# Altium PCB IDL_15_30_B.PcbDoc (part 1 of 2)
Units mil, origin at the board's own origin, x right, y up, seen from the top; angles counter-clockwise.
Board outline 4133.86 x 2440.94 mil, 4 copper layers (Top Layer - SIG1, Layer 2 - GND1, Layer 3 - SIG2, Bottom Layer - SIG4), stack 63.086 mil thick; 140 components, 50 nets, 376 pads, 452 vias.
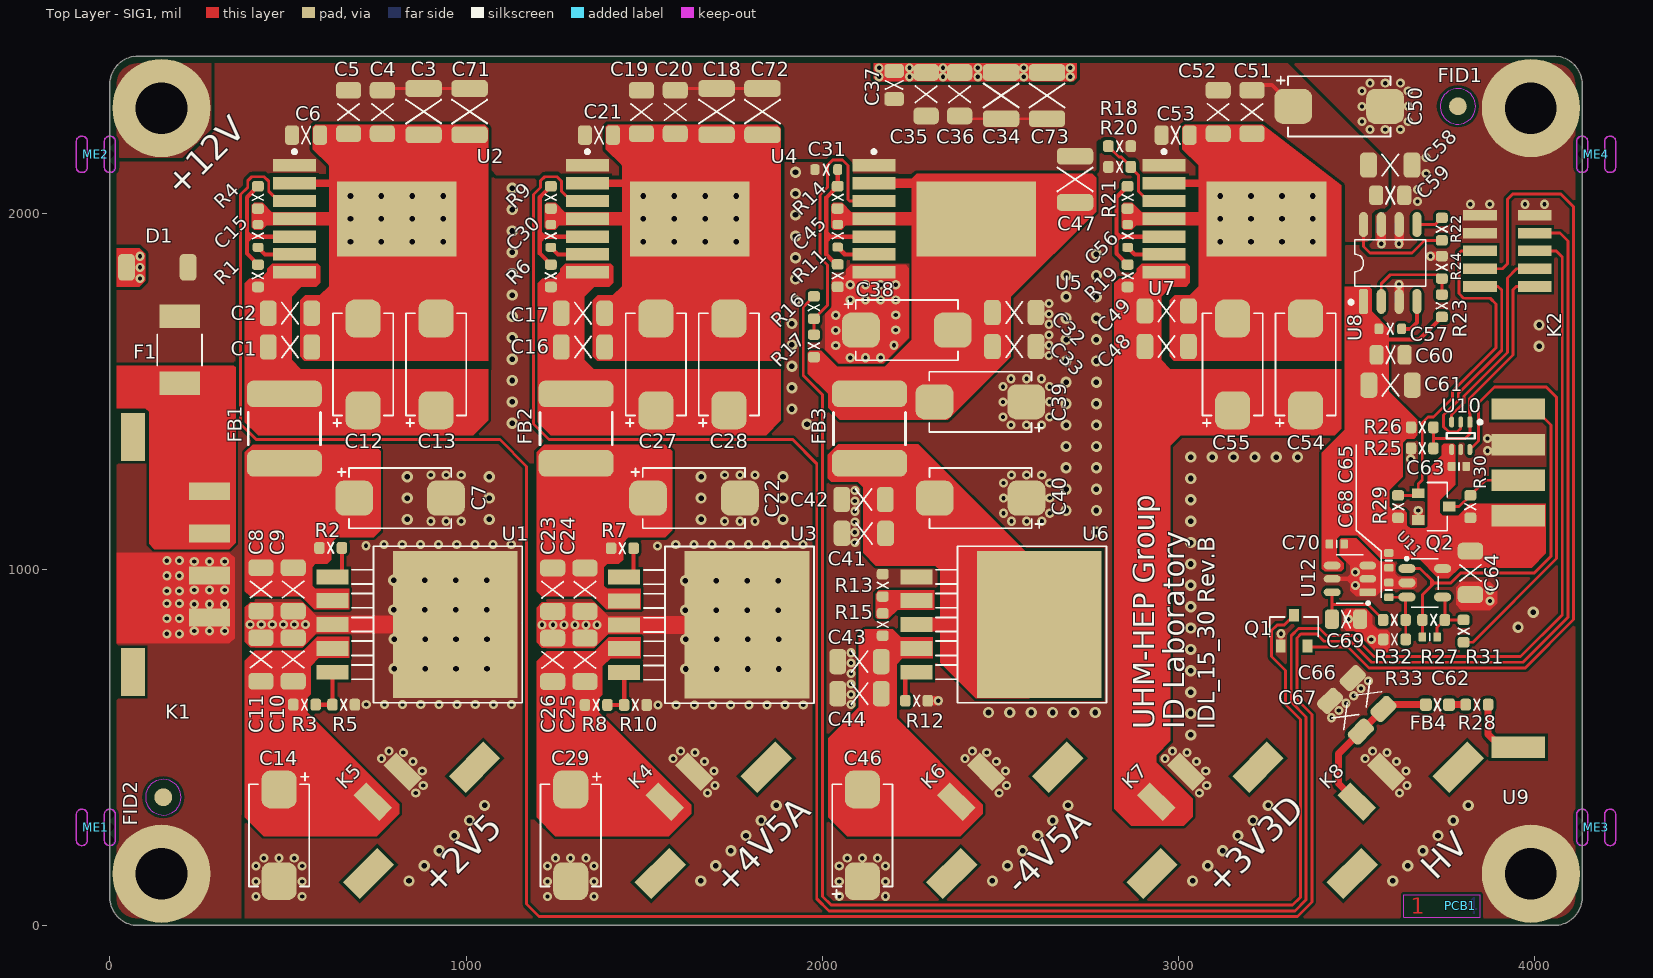
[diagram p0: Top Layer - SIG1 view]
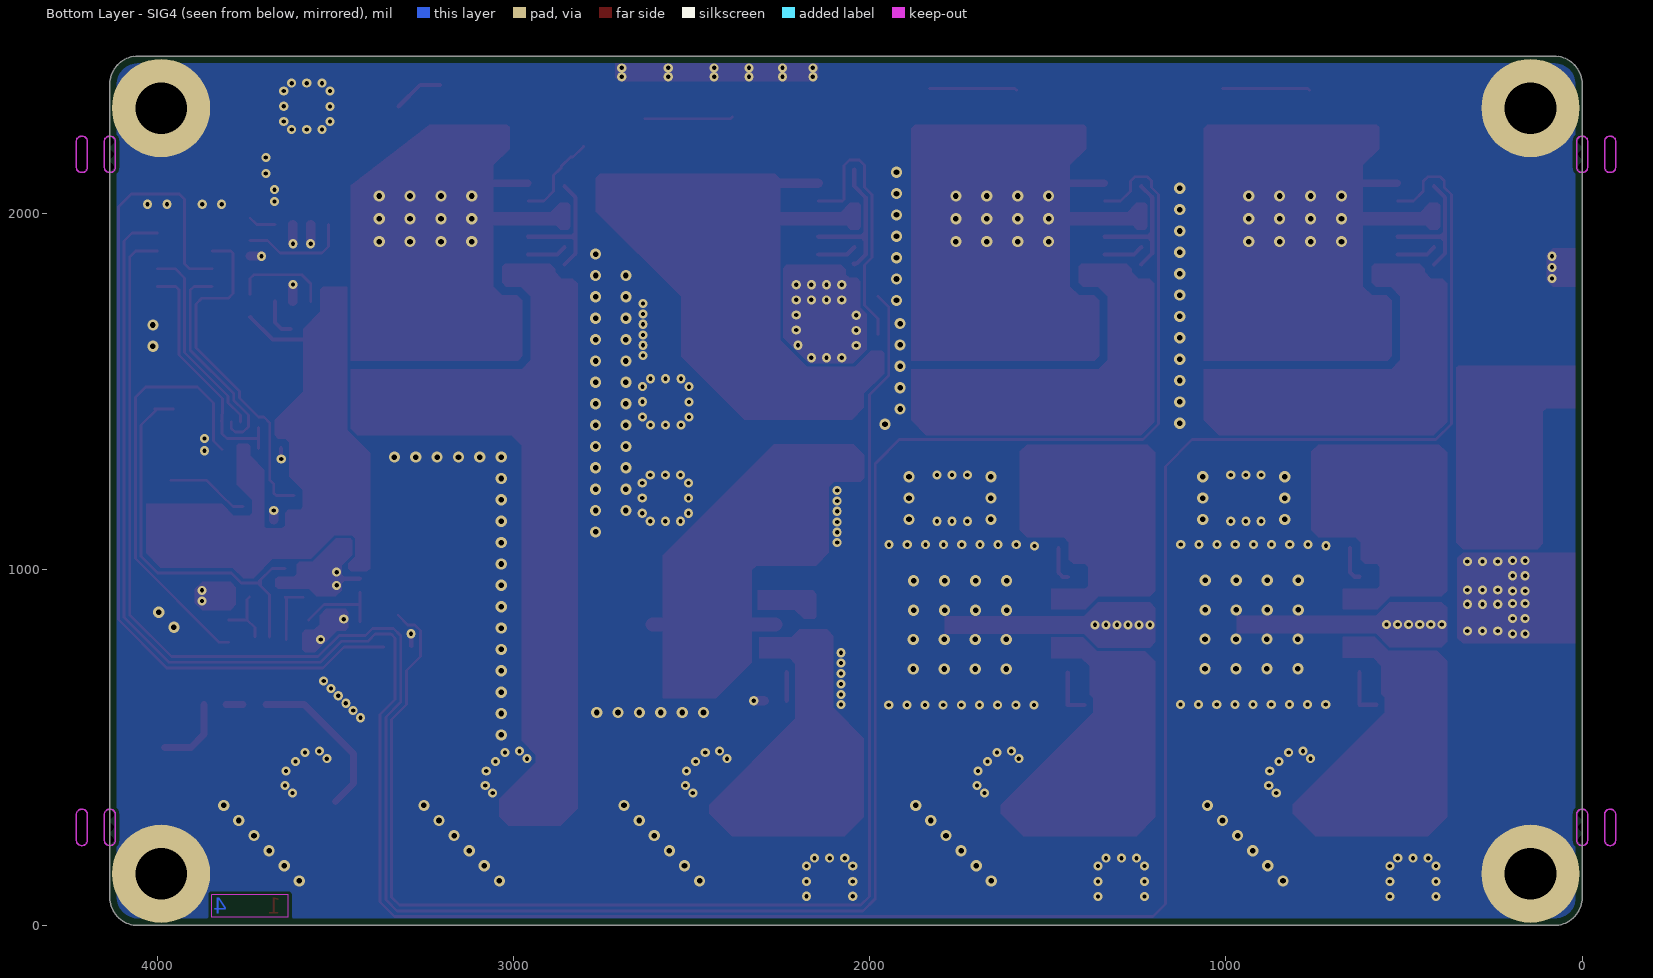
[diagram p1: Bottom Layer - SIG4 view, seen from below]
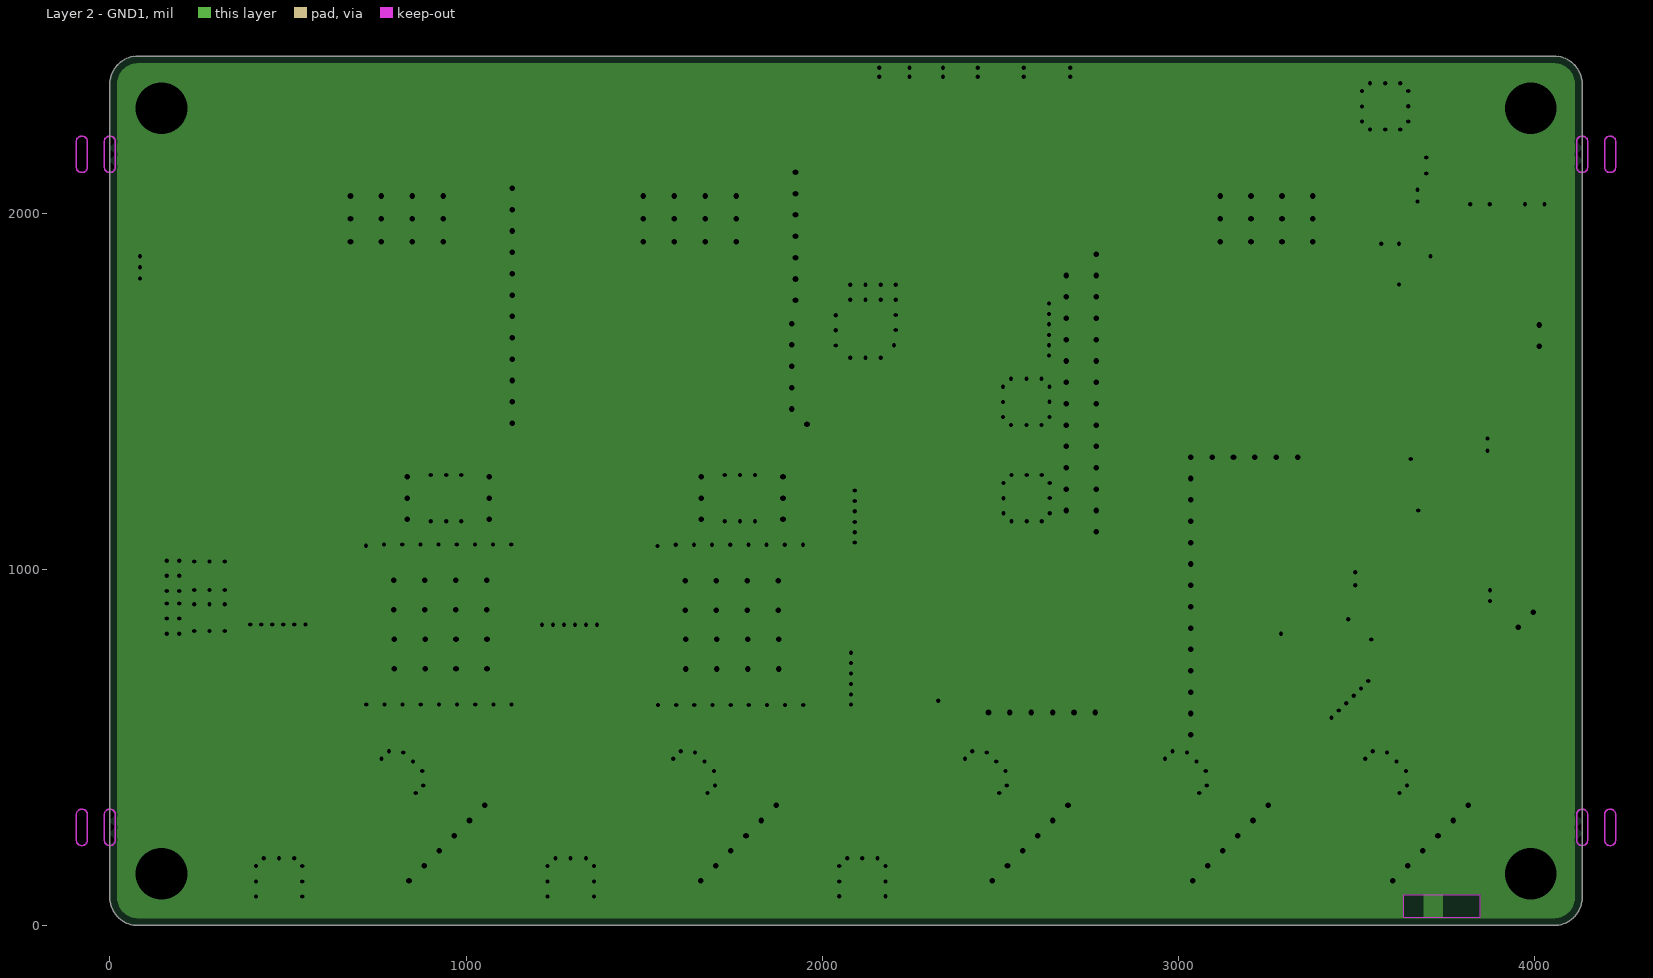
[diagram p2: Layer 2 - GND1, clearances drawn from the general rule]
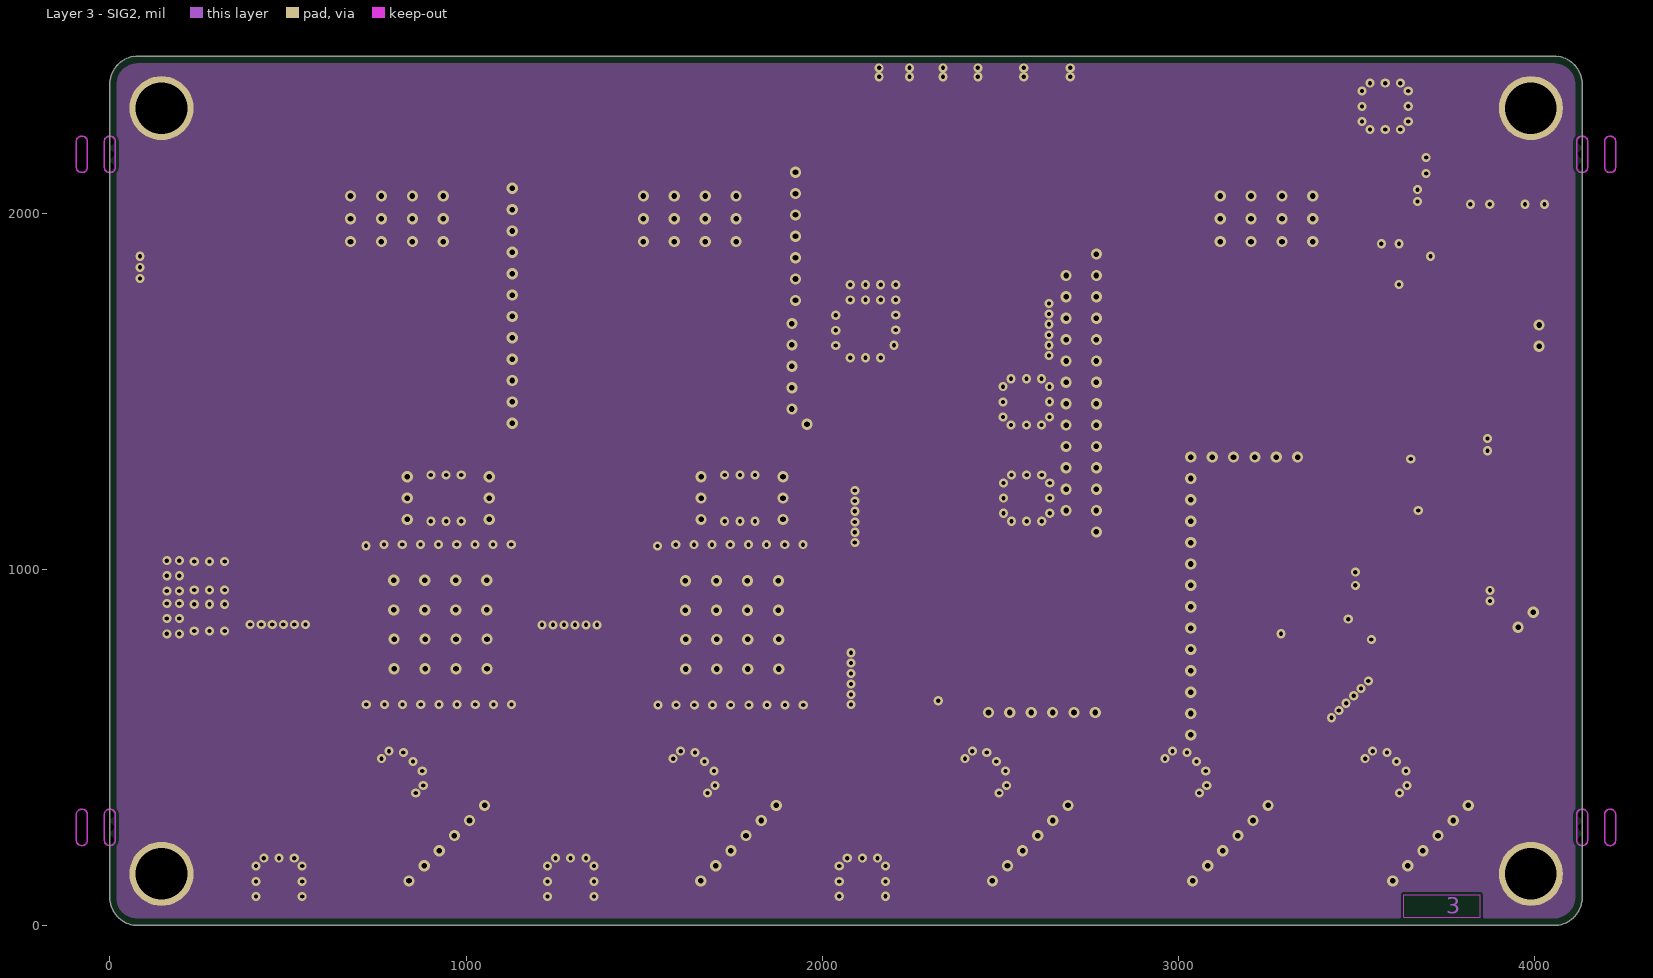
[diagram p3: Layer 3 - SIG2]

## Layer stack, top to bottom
Top Solder: solder mask 0.4, Solder Resist, Dk 3.5
Top Layer - SIG1: signal copper 2.165
Dielectric 1: prepreg 15, FR-4, Dk 4.65
Layer 2 - GND1: plane copper 1.378, net GND
Dielectric 3: core 26, FR-4, Dk 4.65
Layer 3 - SIG2: signal copper 1.378
Dielectric 6: prepreg 15, FR-4, Dk 4.65
Bottom Layer - SIG4: signal copper 2.165
Bottom Solder: solder mask 0.4, Solder Resist, Dk 3.5

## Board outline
78.74,0 cw(c78.74,78.74) 0,78.74 0,2362.2 cw(c78.74,2362.2) 78.74,2440.94 4055.12,2440.94 cw(c4055.12,2362.2) 4133.86,2362.2 4133.86,78.74 cw(c4055.12,78.74) 4055.12,0

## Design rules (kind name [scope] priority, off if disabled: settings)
Clearance Clearance_Diff [InAnyDifferentialPair  or InNetClass('INPUT') vs InNamedPolygon('L4_5VAN') or InNamedPolygon('L3_5VAP') or InNamedPolygon('L4_GND') OR InNamedPolygon('L6_GND')   or InNamedPolygon('L4_GND') or InNamedPolygon('L4_GND')] p1: gap=15
Clearance Clearance_RF [InNetClass('RF') vs InNamedPolygon('L4_GND')  or InNamedPolygon('L4_GND')  or InNamedPolygon('L4_GND')] p2: gap=27.56
Clearance Clearance_Poly [InNamedPolygon('L1_+12V') or InNamedPolygon('L3_5VAP')  or InNamedPolygon('L4_GND')     OR InNamedPolygon('L6_GND')  or InNamedPolygon('L4_GND') or InNamedPolygon('L4_GND')] p3: gap=10
Clearance Clearance_KeepOut [Iskeepout] p4 off: gap=20
Clearance [All] p5: gap=8
ComponentClearance [All] p1 off: gap=10 collisioncheckmode=3 verticalgap=10 showdistances=FALSE
DiffPairsRouting [All] p1: maxlimit=10 minlimit=4.02 mostfreqgap=6 toplayer_minwidth=4.02 toplayer_maxwidth=12.01 toplayer_prefwidth=8 midlayer1_minwidth=4.02 midlayer1_maxwidth=12.01 midlayer1_prefwidth=8 bottomlayer_minwidth=4.02 bottomlayer_maxwidth=12.01 bottomlayer_prefwidth=8 maxuncoupledlength=500
Height [All] p1 off: minheight=0 maxheight=1000 prefheight=500
HoleSize [All] p1 off: absolutevalues=TRUE maxlimit=129.92 minlimit=11.81 maxpercent=80.000 minpercent=20.000
MinimumSolderMaskSliver [All] p1: minsoldermaskwidth=5
NetAntennae [All] p1 off: netantennaetolerance=0
PlaneClearance [All] p1: clearance=10
PlaneConnect PlaneConnect_vIA [ISvIA] p1: planeconnectstyle=Direct reliefexpansion=20 reliefentries=4 reliefconductorwidth=10 reliefairgap=10
PlaneConnect [All] p2: planeconnectstyle=Direct reliefexpansion=12 reliefentries=4 reliefconductorwidth=15 reliefairgap=8
PolygonConnect [IsPad vs InNamedPolygon('L1_+12V')] p1: connectstyle=Direct reliefconductorwidth=10 reliefentries=4 polygonreliefangle="90 Angle" airgapwidth=10
PolygonConnect PolygonConnect_Via [IsVia or HasFootprint('CNSMBPCBH-1') or HasFootprint('BK377') or HasFootprint('SOT89-1') or InPadClass('Free') or HasFootprint('MCV1.5/2G-3.81')    or HasFootprint('CNSMAPCBH-1')] p2: connectstyle=Direct reliefconductorwidth=10 reliefentries=4 polygonreliefangle="90 Angle" airgapwidth=10
PolygonConnect PolygonConnect_Main [All] p3: connectstyle=Direct reliefconductorwidth=12 reliefentries=4 polygonreliefangle="90 Angle" airgapwidth=10
RoutingVias [All] p1: holewidth=11.81 width=25.59 viastyle="Through Hole" minholewidth=11.81 minwidth=25.59 maxholewidth=196.85 maxwidth=393.7
SilkToSilkClearance [All] p1: silktosilkclearance=5
SilkToSolderMaskClearance SilkscreenOverComponentPads [IsPad] p1: minsilkscreentomaskgap=5 clearancetoexposedcopper=TRUE
SolderMaskExpansion [All] p1: expansion=2
Width Width_Logo [HasFootprint('ITECH_LOGO')] p1: maxlimit=10 minlimit=1 preferedwidth=2
Width [All] p2: maxlimit=150 minlimit=3.94 preferedwidth=8 minimp=50.000000 maximp=50.000000 favimp=50.000000
20 further rules are at their usual default settings.

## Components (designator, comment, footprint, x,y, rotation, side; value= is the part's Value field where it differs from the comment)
C1 "10uF" CC1206N1R 505.87,1624.13 r180 top
C2 "10uF" CC1206N1R 505.87,1719.13 r180 top
C3 "100uF" CC1210N1R 881.06,2285 r270 top
C4 "10uF" CC1206N1R 765.12,2284.13 r90 top
C5 "10uF" CC1206N1R 670.12,2284.13 r90 top
C6 "1uF" CC0805N1R 550.87,2219.13 r180 top
C7 "330uF" CTC-D7343-43 815,1200 r0 top
C8 "10uF" CC1206N1R 424.17,943.42 r90 top
C9 "10uF" CC1206N1R 514.72,943.43 r90 top
C10 "10uF" CC1206N1R 514.72,746.57 r270 top
C11 "10uF" CC1206N1R 424.17,746.57 r270 top
C12 "220uF" CTC-D7343-43 710.87,1575.2 r90 top
C13 "220uF" CTC-D7343-43 915.87,1575.2 r90 top
C14 "220uF" CTC-D7343-43 475,252.87 r270 top
C15 "470nF" CC0603RF1R 415.87,1936.13 r270 top
C16 "10uF" CC1206N1R 1328.23,1624.13 r180 top
C17 "10uF" CC1206N1R 1328.23,1719.13 r180 top
C18 "100uF" CC1210N1R 1703.43,2285 r270 top
C19 "10uF" CC1206N1R 1492.48,2284.13 r90 top
C20 "10uF" CC1206N1R 1587.48,2284.13 r90 top
C21 "1uF" CC0805N1R 1373.23,2219.13 r180 top
C22 "330uF" CTC-D7343-43 1640,1200 r0 top
C23 "10uF" CC1206N1R 1243.23,942.56 r90 top
C24 "10uF" CC1206N1R 1333.78,942.56 r90 top
C25 "10uF" CC1206N1R 1333.78,745.71 r270 top
C26 "10uF" CC1206N1R 1243.23,745.71 r270 top
C27 "220uF" CTC-D7343-43 1533.23,1575.2 r90 top
C28 "220uF" CTC-D7343-43 1738.23,1575.2 r90 top
C29 "220uF" CTC-D7343-43 1294.05,252.87 r270 top
C30 "470nF" CC0603RF1R 1238.23,1936.13 r270 top
C31 "22nF" CC0603RF1R 2011.6,2122.5 r180 top
C32 "10uF" CC1206N1R 2539.21,1720.94 r0 top
C33 "10uF" CC1206N1R 2539.21,1625.39 r0 top
C34 "100uF" CC1210N1R 2502.39,2330.13 r90 top
C35 "10uF" CC1206N1R 2292,2334 r270 top
C36 "10uF" CC1206N1R 2386,2334 r270 top
C37 "1uF" CC0805N1R 2202,2360 r270 top
C38 "220uF" CTC-D7343-43 2237.91,1671.57 r0 top
C39 "220uF" CTC-D7343-43 2444.21,1470.19 r180 top
C40 "330uF" CTC-D7343-43 2445,1200 r180 top
C41 "10uF" CC1206N1R 2117,1101 r180 top
C42 "10uF" CC1206N1R 2115.98,1196 r180 top
C43 "10uF" CC1206N1R 2105,740.75 r180 top
C44 "10uF" CC1206N1R 2105,650.75 r180 top
C45 "470nF" CC0603RF1R 2043.6,1936.5 r270 top
C46 "220uF" CTC-D7343-43 2113.05,252.87 r90 top
C47 "10uF" CC1210N1R 2710,2095 r270 top
C48 "10uF" CC1206N1R 2967.25,1625.59 r180 top
C49 "10uF" CC1206N1R 2967.25,1725.59 r180 top
C50 "330uF" CTC-D7343-43 3451.73,2300 r0 top
C51 "10uF" CC1206N1R 3206.85,2284.13 r90 top
C52 "10uF" CC1206N1R 3111.85,2284.13 r90 top
C53 "1uF" CC0805N1R 2992.6,2219.13 r180 top
C54 "220uF" CTC-D7343-43 3357.6,1575.2 r90 top
C55 "220uF" CTC-D7343-43 3152.6,1575.2 r90 top
C56 "470nF" CC0603RF1R 2857.6,1936.13 r270 top
C57 "10nF" CC0603RF1R 3595,1675 r180 top
C58 "10uF" CC1206N1R 3595,2135 r180 top
C59 "1uF" CC0805N1R 3595,2050 r180 top
C60 "1uF" CC0805N1R 3596,1602 r180 top
C61 "10uF" CC1206N1R 3596,1517 r180 top
C62 "100nF" CC0402N1R 3706,810 r180 top
C63 "100nF" CC0402N1R 3788,1289 r0 top
C64 "10uF" CC1206N1R 3820,990 r270 top
C65 "100nF" CC0402N1R 3591,1025 r270 top
C66 "1uF" CC1206N1R 3532.93,651.21 r315 top
C67 "1uF" CC1206N1R 3469.29,587.57 r315 top
C68 "100nF" CC0402N1R 3591,942 r270 top
C69 "1uF" CC0805N1R 3470.87,860.13 r180 top
C70 "100nF" CC0402N1R 3444.87,1071.13 r180 top
C71 "100uF" CC1210N1R 1010,2285 r270 top
C72 "100uF" CC1210N1R 1832.36,2285 r270 top
C73 "100uF" CC1210N1R 2631.33,2330.13 r90 top
D1 "PMEG3050EP" SOD128 133,1847.85 r180 top
F1 "16V 5A" FUSE4532-1 196,1615.85 r90 top
FB1 "74279224151" FB2220N1R 490,1395 r270 top
FB2 "74279224151" FB2220N1R 1309.05,1395 r270 top
FB3 "74279224151" FB2220N1R 2132.91,1395 r270 top
FB4 "600Rac" FB0603N1R 3727.52,620 r180 top
FID1 "FIDRT" FIDRT50 3785,2300 r90 top net-tie
FID2 "FIDRT" FIDRT50 150,360 r90 top net-tie
K1 "43650-0413" CN43650-0413 65,1041.85 r270 top
K2 "IDC10pin LPV" CN_20021521-00010T1LF 3924,1894 r180 top
K4 "43650-0225" CN43650-0225 1694,295 r45 top
K5 "43650-0225" CN43650-0225 875,295 r45 top
K6 "43650-0225" CN43650-0225 2513,295 r45 top
K7 "43650-0225" CN43650-0225 3075,295 r45 top
K8 "43650-0225" CN43650-0225 3637,295 r45 top
ME1 "MILL_EAR" MILLEAR2.0D -39.37,275.59 r270 top
ME2 "MILL_EAR" MILLEAR2.0D -39.37,2165.35 r90 top
ME3 "MILL_EAR" MILLEAR2.0D 4173.23,275.59 r90 top
ME4 "MILL_EAR" MILLEAR2.0D 4173.23,2165.35 r90 top
PCB1 "PCB..." LAYNUM4 3792,56 r0 top
Q1 "BSS84" SOT23-1 3325,828 r90 top
Q2 "Q-MMBF170" SOT23-1 3717,1176 r0 top
R1 "3k0" RC0603N1R 415.87,1824.13 r270 top
R2 "4k7" RC0603N1R 620,1060 r180 top
R3 "11k0" RC0603N1R 546.5,620 r180 top
R4 "1k07" RC0603N1R 415.87,2044.13 r90 top
R5 "10k0" RC0603N1R 656.5,620 r180 top
R6 "5k76" RC0603N1R 1238.23,1824.13 r270 top
R7 "4k7" RC0603N1R 1439.05,1059.13 r180 top
R8 "27k4" RC0603N1R 1365.55,619.13 r180 top
R9 "1k07" RC0603N1R 1238.23,2044.13 r90 top
R10 "10k0" RC0603N1R 1475.55,619.13 r180 top
R11 "6k2" RC0603N1R 2043.6,1824.5 r270 top
R12 "4k7" RC0603N1R 2265,631 r0 top
R13 "2k37" RC0603N1R 2170,955 r90 top
R14 "1k07" RC0603N1R 2043.6,2044.5 r90 top
R15 "2k15" RC0603N1R 2170,845 r90 top
R16 "10k0" RC0603N1R 1977,1735 r270 top
R17 "10k0" RC0603N1R 1977,1627.5 r270 top
R18 "20k" RC0603N1R 2835,2188 r0 top
R19 "3k40" RC0603N1R 2857.6,1824.13 r270 top
R20 "10k0" RC0603N1R 2835,2130 r180 top
R21 "1k07" RC0603N1R 2857.6,2044.13 r90 top
R22 "4k7" RC0603N1R 3740,1955 r270 top
R23 "3k32" RC0603N1R 3740,1740 r270 top
R24 "1k07" RC0603N1R 3740,1847.87 r270 top
R25 "10k0" RC0603N1R 3684.87,1339.56 r180 top
R26 "4k7" RC0603N1R 3684.87,1398.56 r0 top
R27 "12k" RC0603N1R 3717,858 r180 top
R28 "100R" RC0603N1R 3838.5,620 r180 top
R29 "10k0" RC0603N1R 3617,1176 r270 top
R30 "10k0" RC0603N1R 3820,1176 r270 top
R31 "10k0" RC0603N1R 3801,826.5 r270 top
R32 "10k0" RC0603N1R 3606.5,858 r180 top
R33 "12k" RC0603N1R 3607,803 r0 top
U1 "LDO_LT1764AEQ" DDPAK 910,845 r270 top locked
U2 "LMZ23605H" DPAK127P1377X457-7N 518.27,1984.13 r0 top locked
U3 "LDO_LT1764AEQ" DDPAK 1729.05,844.13 r270 top locked
U4 "LMZ23605H" DPAK127P1377X457-7N 1340.63,1984.13 r0 top locked
U5 "LMZ23605H" DPAK127P1377X457-7N 2145,1984.13 r0 top locked
U6 "LDO_LT1185CQ" DDPAK 2550,845 r270 top locked
U7 "LMZ23605H" DPAK127P1377X457-7N 2960,1984.13 r0 top
U8 "LT1763CS8" SOIC8-1 3595,1860 r90 top
U9 "SIP90" SIP90 4005,1450 r90 top
U10 "LTC2630-HZ12" SC70-6 3793,1374.81 r270 top
U11 "LTC2050CS5" SOT23-5 3692,962 r0 top
U12 "LT1790ACS6-4.096" SOT23-6 3481.87,973.13 r180 top

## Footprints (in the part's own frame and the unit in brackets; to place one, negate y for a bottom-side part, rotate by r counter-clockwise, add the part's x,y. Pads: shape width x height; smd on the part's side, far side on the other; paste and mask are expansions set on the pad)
CC0402N1R [mm] "Chip capacitor 0402 ROUND pad"
  rrect30% 0.55x0.65 smd mask+0.025: 1(-0.525,0) 2(0.525,0)
  silkscreen extent 0,-0.25 0,0.25, body extent -0.51,-0.25 0.51,0.25, height 0.5
CC0603RF1R [mil] "Chip capacitor 0603 RF pad ROUNDED PAD"
  rrect50% 25x30 smd: 1(-32,0) 2(32,0)
  silkscreen extent -8,-15 8,15, body extent -30,-15 30,15, height 28
CC0805N1R [mm] "Chip capacitor  0805 ROUND PAD"
  rrect50% 1x1.4 smd: 1(-1,0) 2(1,0)
  silkscreen extent -0.3,-0.62 0.3,0.62, body extent -1,-0.63 1,0.63, height 1
CC1206N1R [mm] "Chip capacitor 1206 ROUNDED PAD"
  rrect50% 1.2x1.8 smd: 1(-1.55,0) 2(1.55,0)
  silkscreen extent -0.58,-0.76 0.58,0.76, body extent -1.6,-0.8 1.6,0.8, height 1.35
CC1210N1R [mm] "Chip capacitor 1210 ROUNDED PAD"
  rrect50% 1.2x2.6 smd: 1(-1.65,0) 2(1.65,0)
  silkscreen extent -0.85,-1.25 0.85,1.25, body extent -1.6,-1.25 1.6,1.25, height 1.5
CN43650-0225 [mm] "CN 2 pin Male vertical SMD R3.0"
  rect 1.3x2.6 smd: 1(1.5,3.4) 2(-1.5,3.4)
  rect 3.5x1.7 smd: MP1(-5.35,0) MP2(5.35,0)
  body extent -6.82,-2.44 6.83,4.04, height 9.93
CN43650-0413 [mm] "CN 4 pin Male right-angle SMD R3.0"
  rect 1.27x2.92 smd: 1(4.5,5.47) 2(1.5,5.47) 3(-1.5,5.47) 4(-4.5,5.47)
  rect 3.43x1.7 smd: MP1(8.385,0) MP2(-8.385,0)
  body extent -9.82,-4.6 9.83,6.14, height 5.69
CN_20021521-00010T1LF [mm] "Pin header 2x5 pin R1.27mm"
  rect 2.4x0.76 smd: 1(-1.95,2.54) 2(1.95,2.54) 3(-1.95,1.27) 4(1.95,1.27) 5(-1.95,0) 6(1.95,0) 7(-1.95,-1.27) 8(1.95,-1.27) 9(-1.95,-2.54) 10(1.95,-2.54)
  body extent -2.75,-6.32 2.75,6.32, height 5.6
CTC-D7343-43 [mm] "Capacitor Tantal Chip D - 7343, H=4.3mm"
  rrect50% 2.7x2.5 smd: 1(-3.275,0) 2(3.275,0)
  silkscreen extent -4.45,-2.15 3.65,2.15, body extent -4,-2.15 4,2.15, height 4.31
DDPAK [mil]
  rect 42x90 smd: 1(-134,-285) 2(-67,-285) 3(0,-285) 4(67,-285) 5(134,-285)
  rect 414.02x350 smd paste-393.7: 3(0,60)
  silkscreen extent -220,-230 220,248, body extent -200,-325 200,230, height 175
DPAK127P1377X457-7N [mm] "D2-PAK, 7-Pads, Body 8.15x8.56mm (max), IPC Medium Density"
  rect 3.06x0.89 smd: 1(0,3.81) 2(0,2.54) 3(0,1.27) 4(0,0) 5(0,-1.27) 6(0,-2.54) 7(0,-3.81)
  rect 8.54x5.35 smd paste-10 mask-10: 4(7.305,0)
  silkscreen extent -0.12,4.66 0.13,4.91, body extent -1.18,-5.08 12.59,5.08, height 4.57
FB0603N1R [mm] "Chip Ferrite Bead, 2-Leads, Body 1,6x0,8mm, IPC Medium Density"
  rrect50% 0.85x0.9 smd: 1(-0.825,0) 2(0.825,0)
  silkscreen extent -0.2,-0.4 0.2,0.4, body extent -0.8,-0.4 0.8,0.4, height 0.8
FB2220N1R [mm] "Chip Ferrite, 2-Leads, Body 5,59x5,08mm, IPC Medium Density"
  rrect50% 1.9x5.35 smd: 1(-2.475,0) 2(2.475,0)
  silkscreen extent -1.15,-2.57 1.15,2.58, body extent -3.05,-2.66 3.05,2.67, height 2.05
FIDRT50 [mil] "Fiducial TOP round 50mil"
  round 50 smd paste-100 mask+25: 0(0,0)
  Top Layer - SIG1 keep-out circle w1: c0,0 r50
FUSE4532-1 [mil] "Chip Fuse, Body 4.5x3.2mm"
  rect 66x114 smd: 1(-94,0) 2(94,0)
  silkscreen extent -43,-63 43,63, body extent -89,-63 89,63, height 34
LAYNUM4 [mil]
  Layer 2 - GND1 region: -48,-33 55.12,-33 55.12,29.99 -48,29.99
  Layer 2 - GND1 region: -159,-33 -104,-33 -104,30 -159,30
  Keep-Out Layer lines w1: -159,-33 55.12,-33 55.12,30 -159,30 -159,-33
MILLEAR2.0D [mm] "Milling ear for PCB cut dual side holes"
  round 0 hole 0.6 unplated: 0(0,1) 0(0,-1) 1(-0.9,-1) 1(0.9,1) 2(-0.9,1) 2(0.9,-1)
  Keep-Out Layer lines w0.102: 0.9,-1.4 ccw(c0.9,-1) 0.9,-0.6 -0.9,-0.6 ccw(c-0.9,-1) -0.9,-1.4 0.9,-1.4 ; 0.9,0.6 ccw(c0.9,1) 0.9,1.4 -0.9,1.4 ccw(c-0.9,1) -0.9,0.6 0.9,0.6
RC0603N1R [mm] "Chip resistor 0603 ROUNDED PAD"
  rrect50% 0.75x0.85 smd: 1(-0.8,0) 2(0.8,0)
  silkscreen extent -0.2,-0.38 0.2,0.38, body extent -0.8,-0.4 0.8,0.4, height 0.46
SC70-6 [mm] "6-Leads, Body 2,0x2,1mm (max), Pitch 0,65mm, IPC Medium Density"
  rrect50% 0.8x0.35 smd mask+0.051: 1(-0.98,0.65)
  oval 0.8x0.35 smd mask+0.051: 2(-0.98,0) 3(-0.98,-0.65) 4(0.98,-0.65) 5(0.98,0) 6(0.98,0.65)
  silkscreen extent -1.1,-1 0.2,1.5, body extent -0.63,-1 0.62,1, height 1.11
SIP90 [mil] "SIP90 Emco HV Power supply"
  body extent -1050,-60 100,100, height 550
SOD128 [mm] "2-Leads, Body 2.7x4.0mm (max), IPC Medium Density"
  rrect50% 1.2x1.9 smd: 1(-2.2,0) 2(2.2,0)
  body extent -2,-1.35 2,1.35, height 1.1
SOIC8-1 [mil]
  rrect50% 70x26 smd: 1(-108,75)
  oval 70x26 smd: 2(-108,25) 3(-108,-25) 4(-108,-75) 5(108,-75) 6(108,-25) 7(108,25) 8(108,75)
  silkscreen extent -115,-100 65,115, body extent -77,-97 77,97, height 75
SOT23-1 [mm]
  rect 0.9x0.7 smd: 1(-1.1,0.95) 2(-1.1,-0.95) 3(1.1,0)
  silkscreen extent -0.43,-1.73 0.97,1.73, body extent -1.28,-1.55 1.28,1.55, height 1.02
SOT23-5 [mil]
  oval 48x25 smd mask+2: 1(-50,40) 2(-50,0) 3(-50,-40) 4(50,-40) 5(50,40)
  silkscreen extent -55,-68 38,72, body extent -50,-61 50,61, height 57
SOT23-6 [mm]
  rrect50% 1.2x0.55 smd mask+0.051: 1(-1.27,0.95)
  oval 1.2x0.55 smd mask+0.051: 2(-1.27,0) 3(-1.27,-0.95) 4(1.27,-0.95) 5(1.27,0) 6(1.27,0.95)
  silkscreen extent -1.4,-1.73 0.97,1.83, body extent -1.5,-1.55 1.5,1.55, height 1.46

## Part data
C1 C2 C4 C5 C8 C9 C10 C11 C16 C17 C19 C20 C23 C24 C25 C26 C32 C33 C35 C36 C41 C42 C43 C44 C48 C49 C51 C52 C58 C61 C64: library part CAPCC1206_10U_16VX7R, "Capacitor chip ceramic 1206 16V X7R"
C3 C18 C34 C71 C72 C73: library part CAPCC1210_100U_16VX5R, "Capacitor chip ceramic 1210 16V X5R"
C6 C21 C37 C53 C59 C60 C69: library part CAPCC0805_1U_25VX7R, "Capacitor chip ceramic 0805 25V X7R"
C7 C22 C40 C50: library part CAPT7343_330U_16V, "Capacitor tantal smd 7343-43 16V 50mResr"
C12 C13 C14 C27 C28 C29 C38 C39 C46 C54 C55: library part CAPT7343_220U_6.3V, "Capacitor Aluminium Polymer, High Ripple, smd 7343-43 6.3V 7mResr"
C15 C30 C45 C56: library part CAPCC0603_1_470N_50VX7R, "Capacitor chip ceramic 0603 25V X7R"
C31: library part CAPCC0603_1_22N_50VX7R, "Capacitor chip ceramic 0603 50V X7R"
C47: library part CAPCC1210_10U_50VX7R, "Capacitor chip ceramic 1210 50V X7R"
C57: library part CAPCC0603_1_10N_50VX7R, "Capacitor chip ceramic 0603 50V X7R"
C62 C63 C65 C68 C70: library part CAPCC0402_100000P_50VX7R, "Capacitor chip ceramic 0402 50V X7R"
C66 C67: library part CAPCC1206_1U_100VX7R, "Capacitor chip ceramic 1206 100V X7R"
D1: library part D-PMEG3050EP, "Schottky diode 6A 30V 500ns 0.36Vf"
F1: library part FUSE-MINISMDC260F/16-2, "PolySwitch Fuse SMD 1812 16V 5A"
FB1 FB2 FB3: library part FB2220-74279224151, "Feritte filter smd 2220 5A 10mRdc 150Rac"
FB4: library part FB0603-600R_0.2A, "Feritte filter smd 0603 0.2A 1Rdc"
FID1 FID2: "Fiducial top round open mask"
K1: library part CN-43650-0413, "Connector Header 4 pin rigth-angle SMD 3mm 4A"
K2: library part CN_IDC10V_SMD1.27, "Connector IDC 10 pin vertical 1.27mm SMD"
K4 K5 K6 K7 K8: library part CN-43650-0225, "Connector Header 2 pin vertical SMD 3mm 4A"
ME1 ME2 ME3 ME4: "Milling ear 2.0mm"
PCB1: library part PCB-FR41.6MM4LAY, "Printed Circuit Board 4 layer FR4 1.6mm 35um Cu"
Q1: library part Q-BSS84, "P-Channel MOSFET 50V 0.13A 10R"
Q2: "N-Channel MOSFET 60V, 0.5A, 0.3W"
R1: library part RES0603-1-3k00-1%100PPM, "Chip Resistor 0603 100mW 1% 100ppm"
R2 R7 R12 R22 R26: library part RES0603-1-4k7-1%100PPM, "Chip Resistor 0603 100mW 1% 100ppm"
R3: library part RES0603-1-11k0-1%100PPM, "Chip Resistor 0603 100mW 1% 100ppm"
R4 R9 R14 R21 R24: library part RES0603-1-1k07-1%100PPM, "Chip Resistor 0603 100mW 1% 100ppm"
R5 R10 R16 R17 R20 R25 R29 R30 R31 R32: library part RES0603-1-10k0-1%100PPM, "Chip Resistor 0603 100mW 1% 100ppm"
R6: library part RES0603-1-5k76-1%100PPM, "Chip Resistor 0603 100mW 1% 100ppm"
R8: library part RES0603-1-27k4-1%100PPM, "Chip Resistor 0603 100mW 1% 100ppm"
R11: library part RES0603-1-6k20-1%100PPM, "Chip Resistor 0603 100mW 1% 100ppm"
R13: library part RES0603-2370-1%100PPM, "Chip Resistor 0603 100mW 1% 100ppm"
R15: library part RES0603-1-2k15-1%100PPM_1, "Chip Resistor 0603 100mW 1% 100ppm"
R18: library part RES0603-1-20k0-1%100PPM, "Chip Resistor 0603 100mW 1% 100ppm"
R19: library part RES0603-1-3.40K-1%100PPM, "Chip Resistor 0603 100mW 1% 100ppm"
R23: library part RES0603-1-3k32-1%100PPM, "Chip Resistor 0603 100mW 1% 100ppm"
R27 R33: library part RES0603-1-12k0-1%100PPM, "Chip Resistor 0603 100mW 1% 100ppm"
R28: library part RES0603-0-100R-1%100PPM, "Chip Resistor 0603 100mW 1% 100ppm"
U1 U3: "Low drop low noise regulator 3A  DDPak"
U2 U4 U5 U7: library part DCDC_LMZ23605H, "3A SIMPLE SWITCHER® Power Module for High Output Voltage"
U6: "Negative Low drop regulator 3A"
U8: library part LDO_LT1763CS8#PBF, "500mA, Low Noise, LDO"
U9: library part HVPS-HV-SIP90, "Regulated, Low Ripple High Voltage DC/DC Converter"
U10: library part DAC_LTC2630-HZ12, "12-Bit Vout DAC 12 bit 4.096IntREF ResetToZero"
U11: library part OPAMP_LTC2050CS5, "Zero-Drift Operational Amplifier"
U12: library part REF_LT1790ACS6-4.096, "Reference 4.096V 10ppm 5mA"

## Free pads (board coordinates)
  rect 150x60 smd: 1(3955,1450) 2(3955,1350) 3(3955,1250) 4(3955,1150) 5(3955,500)
  round 275.59 / inner round 180 / far side round 275.59 hole 145: MH1(145,145) MH1(145,2295) MH1(3990,145) MH1(3990,2295)

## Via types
v1: diameter 25.59, hole 11.81, Top Layer - SIG1 to Bottom Layer - SIG4, tented both sides, 262 vias
v2: diameter 31.5, hole 15.75, Top Layer - SIG1 to Bottom Layer - SIG4, tented both sides, 154 vias
v3: diameter 31.5, hole 15.75, Top Layer - SIG1 to Bottom Layer - SIG4, tented top, 36 vias

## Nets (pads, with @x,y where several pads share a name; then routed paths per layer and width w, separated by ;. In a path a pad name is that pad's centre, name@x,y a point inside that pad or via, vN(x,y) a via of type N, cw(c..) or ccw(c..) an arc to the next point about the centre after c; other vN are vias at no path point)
+2V5_3: C10.2 C11.2 C14.1 K5.2 R3.2 U1.4
+2V5EN: K2.7 U2.3 | length 7957.8
  Top Layer - SIG1 w8: U2.3@518.27,2034.13 473.54,2034.13 446.03,2061.64 446.03,2089.61 433.24,2102.39 398.49,2102.39 387.13,2091.04 387.13,2072.35 367,2052.22 367,1408.03 411.03,1364 1095,1364 1170,1289 1170,60 1205,25 3334.25,25 3375,65.75 3375,592 3333,634 3333,807 3344,818 3389.37,818 3409.37,798 3483.37,798 3542.37,739 3967.63,739 4094,865.37 4094,1922 4072,1944 K2.7@4000.77,1944
+3V3D_3: C48.2 C49.2 C54.1 C55.1 K7.2 R19.2 U7.7
+3VA_SW1_3: C1.2 C2.2 C12.1 C13.1 FB1.1 R1.2 U2.7
+3VA_SW2_3: C7.1 C8.2 C9.2 FB1.2 R2.2 U1.2
+4V5A_3: C25.2 C26.2 C29.1 K4.2 R8.2 U3.4
+5HV: C57.2 C60.2 C61.2 C63.1 C64.1 C65.1 C70.2 pad.4 R23.2 R26.1 R29.2 R30.2 U8.1 U10.4 U11.5 U12.4 | length 598.1
  Top Layer - SIG1 w8: 3567,1051.02 C64.1@3820,1051.02
  Top Layer - SIG1 w12: U8.1@3520,1752 3520,1659 3534,1645 3676.5,1645 R23.2@3740,1708.5
+5VA_SW1_3: C16.2 C17.2 C27.1 C28.1 FB2.1 R6.2 U4.7
+5VA_SW2_3: C22.1 C23.2 C24.2 FB2.2 R7.2 U3.2
+5VAEN: K2.5 U4.3 | length 7034.7
  Top Layer - SIG1 w8: U4.3@1340.63,2034.13 1295.9,2034.13 1268.39,2061.64 1268.39,2089.61 1255.61,2102.39 1220.85,2102.39 1209.5,2091.04 1209.5,2072.35 1189.36,2052.22 1189.36,1408.03 1233.39,1364 1917.36,1364 1985,1296.36 1985,75 2019,41 3327.63,41 3359,72.37 3359,585.37 3317,627.37 3317,813.63 3337.37,834 3396,834 3416,814 3490,814 3549,755 3961,755 4078,872 4078,1877 4061,1894 K2.5@4000.77,1894
+12VIN*_3: F1.1 K1.3 K1.4
+12VIN_3: C3.1 C4.2 C5.2 C6.2 C18.1 C19.2 C20.2 C21.2 C34.1 C35.2 C36.2 C37.2 C47.1 C50.1 C51.2 C52.2 C53.2 C58.2 C59.2 C71.1 C72.1 C73.1 D1.1 F1.2 R18.2 R22.2 U2.1 U4.1 U5.1 U7.1 U8.8 | length 1185.6
  Top Layer - SIG1 w8: C4.2@765.12,2345.16 769.92,2349.96 C3.1@881.06,2349.96 C71.1@1010,2349.96 ; C20.2@1587.48,2345.16 1592.28,2349.96 C18.1@1703.43,2349.96 C72.1@1832.36,2349.96 ; C36.2@2386.45,2269.98 2391.25,2265.17 C34.1@2502.39,2265.17 C73.1@2631.33,2265.17 ; U8.8@3520,1968 3520,1906 3538,1888 3656,1888 3691.5,1923.5 R22.2@3740,1923.5
  Top Layer - SIG1 w12: C51.2@3206.85,2360.16 3262.64,2360.16 C50.1@3322.8,2300
-4V5A_3: C43.1 C44.1 C46.2 K6.2 R15.1 U6.4
-5.4VA_SW1_3: C32.1 C33.1 C38.2 C39.2 C45.1 C47.2 FB3.1 R14.1 R17.2 U5.2 U5.4 | length 219.5
  Top Layer - SIG1 w12: C45.1@2043.6,1968.5 R14.1@2043.6,2013
  Top Layer - SIG1 w26: U5.2@2145,2084.13 U5.4@2320,2084.13
-5.4VA_SW2_3: C40.2 C41.1 C42.1 FB3.2 U6.3 | length 345
  Top Layer - SIG1 w40: U6.3@2265,845 U6.3@2610,845
-5VAEN: K2.4 Q1.2 | length 2456.6
  Top Layer - SIG1 w8: Q1.2@3364,782 3476.75,782 3535.75,723 3974.25,723 4110,858.75 4110,2018 4074,2054 3939,2054 3924,2039 3924,1858 3910,1844 K2.4@3847.23,1844
-5VAEN*: Q1.3 R16.1 | length 3944.7
  Top Layer - SIG1 w8: R16.1@1977,1766.5 1947,1736.5 1947,1544 2001,1490 2001,81.63 2025.63,57 3321,57 3343,79 3343,578.75 3301,620.75 3301,715.8 3261.82,754.98 3261.82,827.88 3277.73,843.8 3297.49,843.8 Q1.3@3325,871.31
GND: C1.1 C2.1 C3.2 C4.1 C5.1 C6.1 C7.2 C8.1 C9.1 C10.1 C11.1 C12.2 C13.2 C14.2 C15.1 C16.1 C17.1 C18.2 C19.1 C20.1 C21.1 C22.2 C23.1 C24.1 C25.1 C26.1 C27.2 C28.2 C29.2 C30.1 C31.2 C32.2 C33.2 C34.2 C35.1 C36.1 C37.1 C38.1 C39.1 C40.1 C41.2 C42.2 C43.2 C44.2 C46.1 C48.1 C49.1 C50.2 C51.1 C52.1 C53.1 C54.2 C55.2 C56.1 C58.1 C59.1 C60.1 C61.1 C63.2 C64.2 C65.2 C66.1 C67.1 C68.1 C69.1 C70.1 C71.2 C72.2 C73.2 D1.2 K1.1 K1.2 K2.8 K2.9 K2.10 K4.1 K5.1 K6.1 K7.1 K8.1 pad.2 pad.MH1 Q1.1 Q2.2 R4.1 R5.1 R9.1 R10.1 R11.2 R12.2 R13.2 R20.2 R21.1 R24.1 R25.2 R33.1 U1.3 U2.2 U2.4 U3.3 U4.2 U4.4 U5.7 U6.1 U7.2 U7.4 U8.3 U8.6 U8.7 U10.5 U11.2 U12.1 U12.2 U12.3 U12.5 | length 6713.5
  Top Layer - SIG1 w12: C15.1@415.87,1968.13 R4.1@415.87,2012.64 ; C11.1@424.17,807.6 C10.1@514.72,807.6 v1@552.13,845 ; C8.1@424.17,882.4 C9.1@514.72,882.4 v1@552.13,845 ; C1.1@566.89,1624.13 630.87,1624.13 C12.2@710.87,1704.13 ; C2.1@566.89,1719.13 695.87,1719.13 C12.2@710.87,1704.13 ; C6.1@590.24,2219.13 666.14,2219.13 C5.1@670.12,2223.11 ; U1.3@625,845 v1@552.13,845 ; C5.1@670.12,2238.11 670.12,2119.88 705.87,2084.13 U2.4@765.12,2024.88 ; C4.1@765.12,2238.11 U2.4@765.12,2024.88 ; C13.2@915.87,1704.13 915.87,1874.13 U2.4@805.87,1984.13 ; C26.1@1243.23,806.73 C25.1@1333.78,806.73 v1@1371.18,844.13 ; C23.1@1243.23,881.54 C24.1@1333.78,881.54 v1@1371.18,844.13 ; C16.1@1389.25,1624.13 1453.23,1624.13 C27.2@1533.23,1704.13 ; C17.1@1389.25,1719.13 1518.23,1719.13 C27.2@1533.23,1704.13 ; C21.1@1412.6,2219.13 1488.5,2219.13 C19.1@1492.48,2223.11 ; U3.3@1444.05,844.13 v1@1371.18,844.13 ; C19.1@1492.48,2238.11 1492.48,2119.88 U4.4@1587.48,2024.88 ; C20.1@1587.48,2238.11 U4.4@1587.48,2024.88 ; C28.2@1738.23,1704.13 1738.23,1874.13 U4.4@1628.23,1984.13 ; C48.1@3008.62,1624.13 3072.6,1624.13 C55.2@3152.6,1704.13 ; C49.1@3008.62,1719.13 3137.6,1719.13 C55.2@3152.6,1704.13 ; C53.1@3031.97,2234.13 3107.87,2234.13 3111.85,2238.11 3111.85,2119.88 U7.4@3206.85,2024.88 ; C51.1@3206.85,2238.11 U7.4@3206.85,2024.88 ; Q1.1@3287.6,784.69 3287.6,818.6 v1(3288,819) ; C54.2@3357.6,1704.13 3357.6,1874.13 U7.4@3247.6,1984.13 ; U12.5@3431.87,973.13 3477,973.13 ; v1(3477,860) 3477.13,860.13 C69.1@3510.24,860.13 3542,828.37 v1(3542,803) R33.1@3575.5,803 ; 3477,973 v1@3495.87,954.13 ; v1@3495.87,992 3477,973.13 ; 3498.87,973.13 3477,973.13 ; v1(3652.62,1309.56) 3653.38,1310.31 R25.2@3653.38,1339.56 ; C12.2@710.87,1704.13 710.87,1889.13 U2.4@805.87,1984.13 ; U2.4@765.12,2024.88 U2.4@805.87,1984.13 ; C27.2@1533.23,1704.13 1533.23,1889.13 U4.4@1628.23,1984.13 ; U4.4@1587.48,2024.88 U4.4@1628.23,1984.13 ; C55.2@3152.6,1704.13 3152.6,1889.13 U7.4@3247.6,1984.13 ; U7.4@3206.85,2024.88 U7.4@3247.6,1984.13 ; C30.1@1238.23,1968.13 R9.1@1238.23,2012.64 C30.1@1238.23,1968.13
  Top Layer - SIG1 w20: U2.2@518.27,2084.13 U2.4@705.87,2084.13 ; U4.2@1340.63,2084.13 U4.4@1528.23,2084.13 ; U7.2@2960,2084.13 U7.4@3147.6,2084.13
  Top Layer - SIG1 w26: R12.2@2296.5,631 v1(2326,631) ; v1(3570,1914) U8.7@3570,1968 ; U8.3@3620,1752 v1(3620,1800) ; v1(3620,1914) U8.6@3620,1968 ; Q2.2@3673.69,1138.6 v1(3673.69,1165.31) ; v1@3708.37,1879.37 R24.1@3740,1879.37
  other v1: 410,81.27 540,81.27 1229.06,81.27 1359.05,81.27 2048,82 2178,82 410,123.61 540,123.61 1229.06,123.61 1359.05,123.61 2048.06,123.61 2178.05,123.61 410,166.61 540,166.61 1229.06,166.61 1359.05,166.61 2048.06,166.61 2178.05,166.61 432.33,188.94 474.67,188.94 517.67,188.94 1251.39,188.94 1293.72,188.94 1336.72,188.94 2070.39,188.94 2112.72,188.94 2155.72,188.94 859,372 1678,372 2497,372 3059,372 3621,372 880,393 1699,393 2518,393 3080,393 3642,393 877,434 1696,434 2515,434 3077,434 3639,434 851,460 1670,460 2489,460 3051,460 3613,460 762.7,468.3 1581.7,468.3 2400.7,468.3 2962.7,468.3 3524.7,468.3 824,486 1643,486 2462,486 3024,486 3586,486 783.7,489.3 1602.7,489.3 2421.7,489.3 2983.7,489.3 3545.7,489.3 3430.49,583.08 3450.76,603.36 1539.05,619.13 1590.05,619.13 1641.05,619.13 1692.05,619.13 1743.05,619.13 1794.05,619.13 1845.05,619.13 1896.05,619.13 1947.05,619.13 720,620 771,620 822,620 873,620 924,620 975,620 1026,620 1077,620 1128,620 2080.74,620.14 3471.27,623.86 3492.48,645.08 2080.74,648.81 3512.99,665.58 2080.74,677.81 3533.5,686.09 2080.74,707.81 2080.74,736.81 2080.74,765.81 160,818.85 195,818.85 237,826.85 280,826.85 322.34,826.85 1213.05,844.13 1244.05,844.13 1275.05,844.13 1306.05,844.13 1337.05,844.13 1368.05,844.13 394,845 425,845 456,845 487,845 518,845 549,845 160,861.85 195,861.85 237,901.85 280,901.85 322.34,901.85 160,904.19 195,904.19 3875,911 160,938.85 195,938.85 3875,941 237,941.85 280,941.85 322.34,941.85 3497,955 160,981.85 195,981.85 3497,992 237,1021.85 280,1021.85 322.34,1021.85 160,1024.19 195,1024.19 1538.05,1065.13 719,1066 1589.05,1069.13 1640.05,1069.13 1691.05,1069.13 1742.05,1069.13 1793.05,1069.13 1844.05,1069.13 1895.05,1069.13 1946.05,1069.13 770,1070 821,1070 872,1070 923,1070 974,1070 1025,1070 1076,1070 1127,1070 2091.72,1075.39 2091.72,1104.06 2091.72,1133.06 901.27,1135 944.27,1135 986.61,1135 1726.27,1135 1769.27,1135 1811.61,1135 2531.27,1135 2574.27,1135 2616.61,1135 2508.94,1157.33 2638.94,1157.33 2091.72,1163.06 2091.72,1192.06 2508.94,1199.67 2638.94,1200.33 2091.72,1221.06 2508.94,1242.67 2638.94,1242.67 901.27,1265 944.27,1265 986.61,1265 1726.27,1265 1769.27,1265 1811.61,1265 2531.27,1265 2574.27,1265 2616.61,1265 3868,1333 3868,1367 2530.48,1405.19 2573.48,1405.19 2615.82,1405.19 2508.15,1427.52 2638.15,1427.52 2508.15,1469.86 2638.15,1470.52 2508.15,1512.86 2638.15,1512.86 2530.48,1535.19 2573.48,1535.19 2615.82,1535.19 2079,1594 2122,1594 2164.34,1594 2637,1600.33 2038,1628 2202,1629 2637,1629 2637,1658 2038,1671 2206.68,1671.98 2637,1688 2038,1713.34 2206.68,1714.32 2637,1717 2637,1746 2079,1756.66 2122,1756.66 2164.34,1756.66 2206.68,1756.66 2079,1799 2122,1799 2164.34,1799 2206.68,1799 85,1816.85 85,1847.85 85,1878.85 3708,1879 3820,2025 3874.46,2025 3973.54,2025 4028,2025 3672,2033 3672,2066 3696,2111 3696,2156 3538,2235 3581,2235 3623.34,2235 3515.67,2257.33 3645.67,2257.33 3515.67,2299.67 3645.67,2300.33 3515.67,2342.67 3645.67,2342.67 3538,2365 3581,2365 3623.34,2365 2160,2383 2245,2383 2339,2383 2437.06,2383 2566,2383 2696.66,2383 2160,2408 2245,2408 2339,2408 2437.06,2408 2566,2408 2696.66,2408
  other v2: 840,125 1659,125 2478,125 3040,125 3602,125 882.43,167.43 1701.43,167.43 2520.43,167.43 3082.43,167.43 3644.43,167.43 924.85,209.85 1743.85,209.85 2562.85,209.85 3124.85,209.85 3686.85,209.85 967.28,252.28 1786.28,252.28 2605.28,252.28 3167.28,252.28 3729.28,252.28 1009.71,294.71 1828.71,294.71 2647.71,294.71 3209.71,294.71 3771.71,294.71 1052.13,337.13 1871.13,337.13 2690.13,337.13 3252.13,337.13 3814.13,337.13 3035,535 3035,595 2467,598 2527,598 2587,598 2647,598 2707,598 2767,598 3035,655 3035,715 1617.05,720.13 1704.05,720.13 1791.05,720.13 1878.05,720.13 798,721 885,721 972,721 1059,721 3035,775 1617.05,803.13 1704.05,803.13 1791.05,803.13 1878.05,803.13 798,804 885,804 972,804 1059,804 3035,835 3954,837 3996.43,879.43 1616.05,885.13 1703.05,885.13 1790.05,885.13 1877.05,885.13 797,886 884,886 971,886 1058,886 3035,895 3035,955 1616.05,968.13 1703.05,968.13 1790.05,968.13 1877.05,968.13 797,969 884,969 971,969 1058,969 3035,1015 3035,1075 2770,1105 3035,1135 835,1140 1065,1140 1660,1140 1890,1140 2685,1165 2770,1165 3035,1195 835,1200 1065,1200 1660,1200 1890,1200 2685,1225 2770,1225 3035,1255 835,1260 1065,1260 1660,1260 1890,1260 2685,1285 2770,1285 3035,1315 3095,1315 3155,1315 3215,1315 3275,1315 3335,1315 2685,1345 2770,1345 2685,1405 2770,1405 1957.43,1407.57 1130,1410 1915,1450 2685,1465 2770,1465 1130,1470 1915,1510 2685,1525 2770,1525 1130,1530 1915,1570 2685,1585 2770,1585 1130,1590 4013,1626 1915,1630 2685,1645 2770,1645 1130,1650 4013,1686 1915,1690 2685,1705 2770,1705 1130,1710 1925,1755 2685,1765 2770,1765 1130,1770 1925,1815 2685,1825 2770,1825 1130,1830 1925,1875 2770,1885 1130,1890 1925,1935 1130,1950 1925,1995 1130,2010 1925,2055 1130,2070 1925,2115
  other v3: 675.75,1920.16 762.36,1920.16 849.37,1920.16 935.98,1920.16 1498.11,1920.16 1584.72,1920.16 1671.73,1920.16 1758.35,1920.16 3117.48,1920.16 3204.09,1920.16 3291.1,1920.16 3377.72,1920.16 675.75,1984.13 762.36,1984.13 849.37,1984.13 935.98,1984.13 1498.11,1984.13 1584.72,1984.13 1671.73,1984.13 1758.35,1984.13 3117.48,1984.13 3204.09,1984.13 3291.1,1984.13 3377.72,1984.13 675.75,2048.11 762.36,2048.11 849.37,2048.11 935.98,2048.11 1498.11,2048.11 1584.72,2048.11 1671.73,2048.11 1758.35,2048.11 3117.48,2048.11 3204.09,2048.11 3291.1,2048.11 3377.72,2048.11
HV_BIAS_3: C66.2 C67.2 FB4.2 K8.2 | length 457.3
  Top Layer - SIG1 w20: K8.2@3500.59,347.89 3450,398.48 3450,481.98 3588.02,620 FB4.2@3695.04,620
HVDAC_CS#: K2.1 R25.1 R26.2 U10.1 | length 687.6
  Top Layer - SIG1 w8: R25.1@3716.37,1339.56 R26.2@3716.37,1398.56 ; 3717,1367.56 3805.43,1367.56 3818.59,1380.72 U10.1@3818.59,1413.39 ; 3818,1437.8 3818,1480 3940,1602 3940,1785 3949,1794 K2.1@4000.77,1794 ; 3818.59,1435.97 U10.1@3818.59,1413.39 ; U10.1@3821.5,1416.31 U10.1@3818.59,1413.39
HVDAC_SCK: K2.2 U10.2 | length 592.1
  Top Layer - SIG1 w8: U10.2@3793,1413.39 3793,1395.73 3782.91,1385.65 3759.59,1385.65 3745,1400.23 3745,1433.37 3756.1,1444.46 3786,1474.37 3786,1493.25 3908,1615.25 3908,1784 3898,1794 K2.2@3847.23,1794
HVDAC_SDI: K2.3 U10.3 | length 557
  Top Layer - SIG1 w8: U10.3@3767.41,1413.39 3767.41,1433.15 3802,1467.74 3802,1486.63 3924,1608.63 3924,1818 3950,1844 K2.3@4000.77,1844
